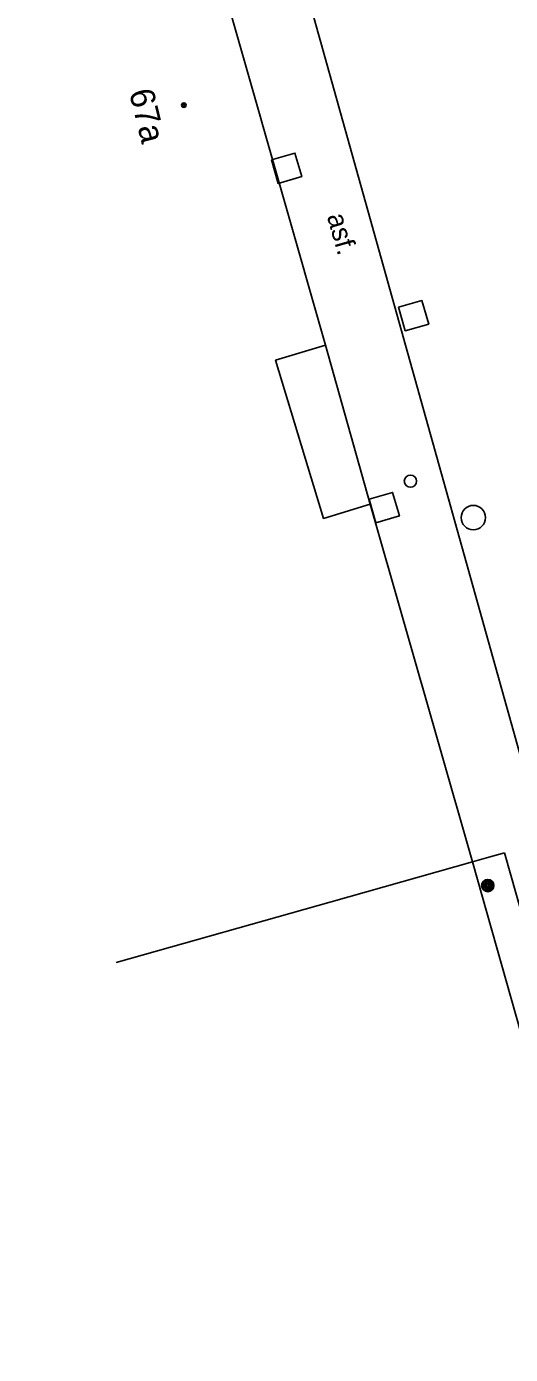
# Model space of a CAD drawing. Extents: x -599098 to -598820, y -1159597 to -1158744.
# Drawn here: x -599029.3 to -599009.6, y -1159044.8 to -1158990.5 of the extents above; entities that cross this region are included whole.
import ezdxf

# ---------------------------------------------------------------- set-up
doc = ezdxf.new("R2010")
doc.units = 0
for name, color, linetype in [('budovy', 7, 'Continuous'), ('kresba', 7, 'Continuous'), ('popisy', 7, 'Continuous'), ('popisy budov', 7, 'Continuous'), ('značky IS', 7, 'Continuous')]:
    doc.layers.add(name, color=color, linetype=linetype)

msp = doc.modelspace()

# ---------------------------------------------------------------- linework, layer by layer
at = {"layer": 'budovy'}
for p, q in [((-598989.86, -1159099.94), (-599011.12, -1159024.69)), ((-599009.81, -1159024.32), (-598989.59, -1159095.91))]:
    msp.add_line(p, q, dxfattribs=at)
for points in [[(-599029.33, -1158960.69), (-599017.12, -1159003.55), (-599015.29, -1159010.06), (-599011.12, -1159024.69)], [(-599015.29, -1159010.06), (-599017.2, -1159010.64), (-599019.16, -1159004.17), (-599017.12, -1159003.55)], [(-599025.668, -1159028.805), (-599016.89, -1159026.32), (-599011.12, -1159024.69), (-599010.54, -1159024.53), (-599009.81, -1159024.32)]]:
    msp.add_lwpolyline(points, dxfattribs=at)
for radius in [0.09, 0.0398]:
    msp.add_circle((-599022.907, -1158993.74), radius, dxfattribs=at)
at = {"layer": 'kresba'}
msp.add_lwpolyline([(-599003.23, -1159028.72), (-599006.28, -1159030.53), (-599008.35, -1159023.24), (-599022.81, -1158971.47), (-599026.53, -1158958.29)], dxfattribs=at)
at = {"layer": 'značky IS'}
for points in [[(-599019.329, -1158995.978), (-599019.053, -1158996.939), (-599018.092, -1158996.663), (-599018.368, -1158995.702)], [(-599014.139, -1159002.008), (-599013.863, -1159002.969), (-599012.902, -1159002.693), (-599013.178, -1159001.732)], [(-599015.339, -1159009.858), (-599015.063, -1159010.819), (-599014.102, -1159010.543), (-599014.378, -1159009.582)]]:
    msp.add_lwpolyline(points, close=True, dxfattribs=at)
for centre, radius in [((-599013.65, -1159009.12), 0.25), ((-599011.08, -1159010.61), 0.5), ((-599010.49, -1159025.66), 0.25), ((-599010.49, -1159025.66), 0.2), ((-599010.49, -1159025.66), 0.15), ((-599010.49, -1159025.66), 0.1), ((-599010.49, -1159025.66), 0.05)]:
    msp.add_circle(centre, radius, dxfattribs=at)

# ---------------------------------------------------------------- texts
at = {"layer": 'popisy'}
msp.add_text('asf.', height=0.8, rotation=285.9115, dxfattribs=at).set_placement((-599017.066, -1158998.276))
at = {"layer": 'popisy budov'}
msp.add_text('67a', height=1, rotation=283.77, dxfattribs=at).set_placement((-599025.15, -1158993.197))

doc.saveas('drawing.dxf')
